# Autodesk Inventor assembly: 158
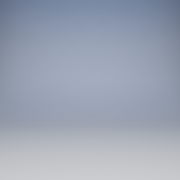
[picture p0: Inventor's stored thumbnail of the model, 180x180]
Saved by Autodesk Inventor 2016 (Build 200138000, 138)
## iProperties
Created: 2016-06
Part Number: 158
Material: Genérico
Document SubType Name: Assembly
Designer: adm
Author: adm
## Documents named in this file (1)
- C:\Users\adm\Desktop\recepcion 2\158.iam
